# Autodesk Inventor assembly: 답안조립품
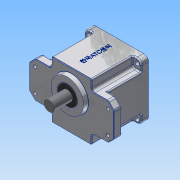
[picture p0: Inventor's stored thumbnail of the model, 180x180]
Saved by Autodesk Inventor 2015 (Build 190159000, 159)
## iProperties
Created: 2016-02
Part Number: 답안조립품
Document SubType Name: Assembly
Designer: Administrator
Author: Administrator
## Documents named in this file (10)
- C:\Users\Administrator\Desktop\460209V1004\답안조립품.iam
- C:\Users\Administrator\Desktop\460209V1004\본체.ipt
- C:\Users\Administrator\Desktop\460209V1004\커버.ipt
- C:\Users\Administrator\Desktop\460209V1004\볼트 M4 x 10.ipt
- C:\Users\Administrator\Desktop\460209V1004\오일실 8 22 7.ipt
- C:\Users\Administrator\Desktop\460209V1004\오일실 17 32 8.ipt
- C:\Users\Administrator\Desktop\460209V1004\베어링 608.ipt
- C:\Users\Administrator\Desktop\460209V1004\서브축.ipt
- C:\Users\Administrator\Desktop\460209V1004\베어링 6003.ipt
- C:\Users\Administrator\Desktop\460209V1004\메인축.ipt
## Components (2 placed, 1 different names)
1. ISO 4762 M4 x 10:1 — Insert:1
2. ISO 4762 M4 x 10:2 — Insert:2
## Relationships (2: Insert 2)
- Insert:1: ISO 4762 M4 x 10:1
- Insert:2: ISO 4762 M4 x 10:2
